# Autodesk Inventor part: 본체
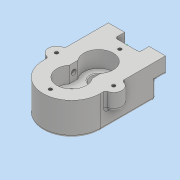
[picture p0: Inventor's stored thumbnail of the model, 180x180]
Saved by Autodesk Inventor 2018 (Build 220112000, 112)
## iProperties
Created: 2024-03
Part Number: 본체
Material: 일반
Document SubType Name: Modeling
Designer: home
Density: 1 g/cm^3
Appearance: 기본값
Mass: 239.342 g
Surface Area: 389.369 cm^2
Volume: 239.342 cm^3
Author: home
## Parameters: d7 = 103 mm, d8 = 0, d9 = 35 mm, d10 = 60 deg, d13 = 35 mm, d14 = 14 mm, d20 = 90 deg, d21 = 33 mm, d22 = 15 mm, d24 = 103 mm, d25 = 0, d27 = 0, d28 = 36 mm, d29 = 36 mm, d30 = 14 mm, d31 = 14 mm, d33 = 0, d41 = 15 mm, d42 = 15 mm, d43 = 12 mm, d44 = 0, d45 = 32 mm, d46 = 52 mm, d47 = 6 mm, d48 = 0, d50 = 0, d52 = 30 deg, d53 = 25 mm, d54 = 7.3 mm, d55 = 0.7 mm, d56 = 90 deg, d57 = 63.5 mm, d58 = 63.5 mm, d63 = 0, d64 = 26 mm, d65 = 26 mm, d66 = 4.134 mm, d68 = 4 mm, d69 = 2 mm, d70 = 90 deg, d71 = 12 mm, d72 = 118 deg, d77 = 42 mm, d80 = 360 deg, d82 = 3.242 mm, d83 = 8 mm, d84 = 3.023 mm, d85 = 2 mm, d86 = 82 deg, d88 = 118 deg, d90 = 0, d91 = 0.5 mm, d92 = 0, d94 = 10 mm, d97 = 6 mm, d98 = 6 mm, d104 = 63.5 mm, d105 = 8 mm, d106 = 55.5 mm, d107 = 0, d108 = 0, d115 = 3 mm, d116 = 3 mm, d117 = 3 mm, d118 = 3 mm, d119 = 3 mm, d120 = 3 mm, d121 = 3 mm, d122 = 1 mm, d123 = 2 mm, d124 = 45 deg, d125 = 1 mm, d126 = 2 mm, d127 = 45 deg, d130 = 8.376 mm, d131 = 14 mm, d132 = 3.023 mm, d133 = 2 mm, d134 = 82 deg, d135 = 16 mm, d136 = 118 deg, d139 = 8.376 mm, d140 = 14 mm, d141 = 3.023 mm, d142 = 2 mm, d143 = 82 deg, d144 = 16 mm, d145 = 118 deg
